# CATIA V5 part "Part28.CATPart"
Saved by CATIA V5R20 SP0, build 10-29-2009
Part number: 9FP041016-20130117
Revision: ANY
Definition: UNKNOWN
Nomenclature: 9FP041016-20130117
Source: Unknown
Bounding box of the stored display mesh (mm): x -8 to 8, y -8 to 8, z 0 to 8
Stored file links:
  C:\Users\Utente\Desktop\IO LAVORO\3D X SITO CF\CUMSA\3D files PF\PF 104200\Part28.CATPart
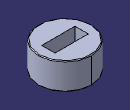
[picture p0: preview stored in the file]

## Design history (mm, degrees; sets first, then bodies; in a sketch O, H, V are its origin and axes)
Body1 "Chaflán1" (main body)
  Solid1: solid without history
